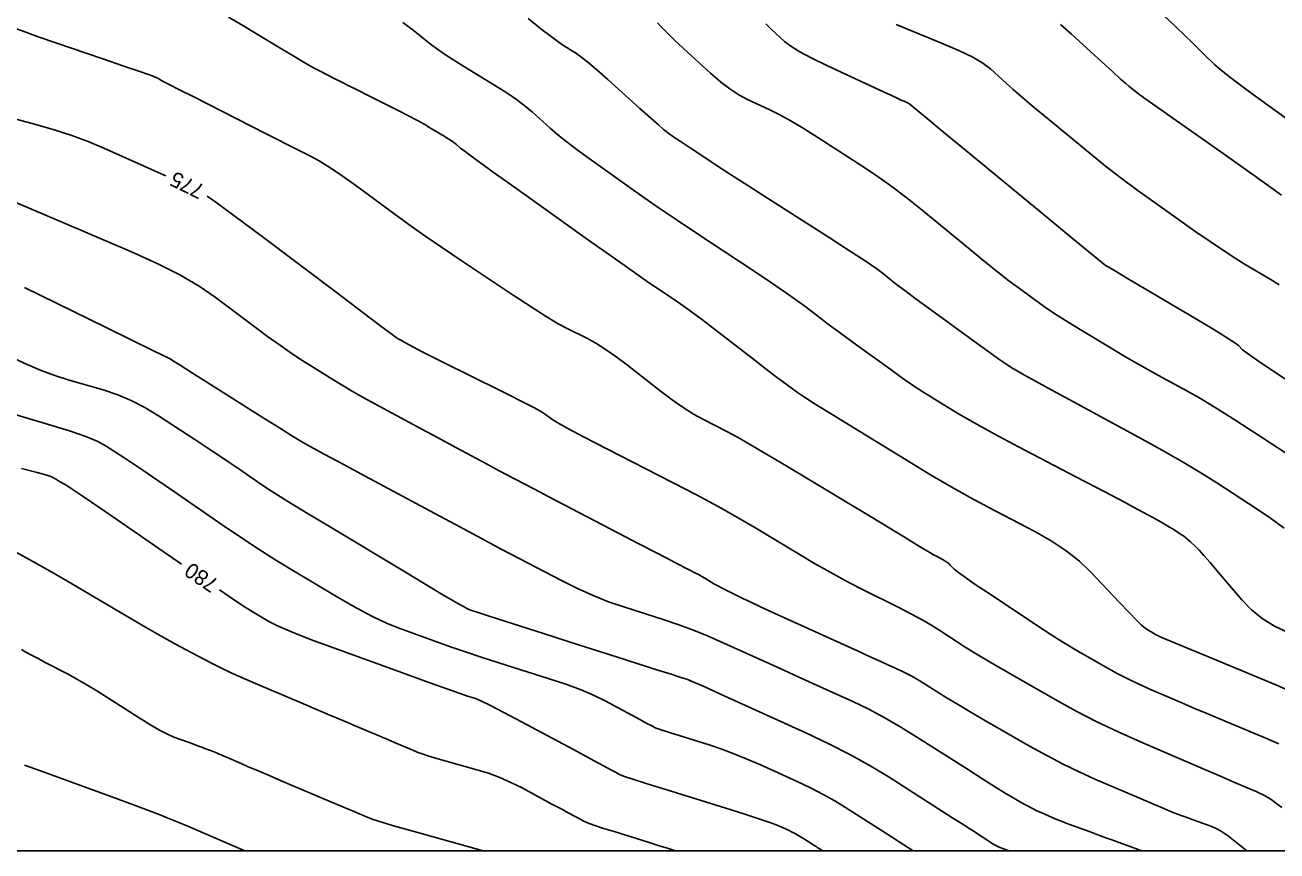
# Model space of a CAD drawing. Extents: x 2082232 to 2083549, y 592624 to 593832.
# Drawn here: x 2082311.6 to 2082368.9, y 592623.8 to 592661.6 of the extents above; entities that cross this region are included whole.
import ezdxf

# ---------------------------------------------------------------- set-up
doc = ezdxf.new("R2010")
doc.units = 0
for name, color, linetype in [('DT_X_Contour_Major', 7, 'Continuous'), ('DT_X_Contour_Minor', 7, 'Continuous'), ('DT_X_TIN_Hull', 7, 'Continuous')]:
    doc.layers.add(name, color=color, linetype=linetype)

msp = doc.modelspace()

# ---------------------------------------------------------------- linework, layer by layer
at = {"layer": 'DT_X_Contour_Major'}
for points in [[(2082340.527, 592661.707), (2082340.704, 592661.507), (2082340.963, 592661.244), (2082341.303, 592660.917), (2082341.725, 592660.527), (2082342.957, 592659.402), (2082343.409, 592659.01), (2082343.842, 592658.68), (2082344.255, 592658.41), (2082344.649, 592658.201), (2082345.672, 592657.726), (2082346.096, 592657.513), (2082346.603, 592657.231), (2082347.192, 592656.88), (2082347.862, 592656.459), (2082349.76, 592655.243), (2082350.479, 592654.766), (2082351.211, 592654.244), (2082351.958, 592653.678), (2082352.719, 592653.069), (2082354.766, 592651.384), (2082355.484, 592650.798), (2082356.101, 592650.303), (2082356.618, 592649.9), (2082357.035, 592649.588), (2082358.013, 592648.878), (2082358.404, 592648.603), (2082358.845, 592648.31), (2082359.335, 592647.998), (2082359.874, 592647.669), (2082361.377, 592646.765), (2082361.93, 592646.436), (2082362.462, 592646.128), (2082362.972, 592645.838), (2082363.461, 592645.569), (2082364.735, 592644.878), (2082365.307, 592644.552), (2082366.065, 592644.091), (2082367.009, 592643.495), (2082368.14, 592642.766), (2082371.406, 592640.64)], [(2082309.776, 592657.658), (2082312.069, 592657.052), (2082312.908, 592656.814), (2082313.706, 592656.555), (2082314.462, 592656.275), (2082315.177, 592655.973), (2082317.028, 592655.142), (2082317.66, 592654.858), (2082318.023, 592654.696)], [(2082319.902, 592653.772), (2082320.298, 592653.499), (2082321.194, 592652.847), (2082322.37, 592651.969), (2082325.875, 592649.324), (2082327.03, 592648.454), (2082327.863, 592647.826), (2082328.376, 592647.442), (2082328.568, 592647.301), (2082328.652, 592647.247), (2082328.707, 592647.215), (2082328.81, 592647.158), (2082328.96, 592647.077), (2082329.157, 592646.97), (2082329.746, 592646.653), (2082330.033, 592646.503), (2082330.452, 592646.29), (2082331.003, 592646.015), (2082331.686, 592645.677), (2082333.684, 592644.691), (2082334.353, 592644.357), (2082334.862, 592644.095), (2082335.211, 592643.903), (2082335.4, 592643.783), (2082335.689, 592643.558), (2082335.927, 592643.411), (2082336.421, 592643.139), (2082337.173, 592642.742), (2082338.183, 592642.221), (2082341.217, 592640.665), (2082342.307, 592640.098), (2082343.298, 592639.564), (2082344.192, 592639.064), (2082344.989, 592638.597), (2082346.982, 592637.396), (2082347.719, 592636.96), (2082348.433, 592636.555), (2082349.124, 592636.179), (2082349.793, 592635.833), (2082351.548, 592634.95), (2082352.16, 592634.636), (2082352.683, 592634.355), (2082353.114, 592634.107), (2082353.456, 592633.893), (2082354.245, 592633.367), (2082354.612, 592633.133), (2082355.118, 592632.825), (2082355.765, 592632.444), (2082356.553, 592631.988), (2082358.84, 592630.675), (2082359.72, 592630.189), (2082360.646, 592629.713), (2082361.618, 592629.248), (2082362.636, 592628.793), (2082365.41, 592627.596), (2082366.333, 592627.199), (2082367.018, 592626.904), (2082367.467, 592626.711), (2082367.68, 592626.62), (2082367.932, 592626.516), (2082368.025, 592626.476), (2082368.115, 592626.434), (2082368.202, 592626.391), (2082368.285, 592626.347), (2082368.505, 592626.227), (2082368.627, 592626.147), (2082368.828, 592625.999), (2082369.107, 592625.781)], [(2082311.403, 592641.311), (2082312.118, 592641.123), (2082312.565, 592641), (2082312.744, 592640.944), (2082312.866, 592640.881), (2082312.92, 592640.852), (2082312.99, 592640.812), (2082313.078, 592640.762), (2082313.182, 592640.701), (2082313.483, 592640.524), (2082313.726, 592640.366), (2082314.229, 592640.027), (2082314.992, 592639.506), (2082316.016, 592638.803), (2082318.738, 592636.93)], [(2082320.472, 592635.744), (2082320.966, 592635.41), (2082321.576, 592635.005), (2082321.968, 592634.757), (2082322.726, 592634.303), (2082323.127, 592634.098), (2082323.764, 592633.826), (2082324.637, 592633.485), (2082325.745, 592633.075), (2082329.014, 592631.893), (2082330.106, 592631.498), (2082330.93, 592631.202), (2082331.488, 592631.005), (2082331.778, 592630.906), (2082332.194, 592630.774), (2082332.443, 592630.67), (2082332.875, 592630.459), (2082333.492, 592630.141), (2082334.293, 592629.715), (2082336.674, 592628.435), (2082337.464, 592628.01), (2082338.049, 592627.696), (2082338.428, 592627.492), (2082338.601, 592627.399), (2082338.79, 592627.298), (2082338.978, 592627.225), (2082339.402, 592627.083), (2082340.061, 592626.872), (2082340.956, 592626.592), (2082343.656, 592625.752), (2082344.564, 592625.466), (2082345.264, 592625.239), (2082345.756, 592625.07), (2082346.039, 592624.959), (2082346.518, 592624.742), (2082346.692, 592624.66), (2082346.853, 592624.577), (2082347.003, 592624.494), (2082347.142, 592624.41), (2082347.495, 592624.184), (2082347.612, 592624.109), (2082347.7, 592624.053), (2082347.759, 592624.015), (2082347.788, 592623.996), (2082347.844, 592623.96), (2082347.894, 592623.927), (2082348.091, 592623.798)]]:
    msp.add_lwpolyline(points, dxfattribs=at)
at = {"layer": 'DT_X_Contour_Minor'}
for points in [[(2082363.073, 592662.646), (2082364.254, 592661.516), (2082364.666, 592661.122), (2082365.016, 592660.786), (2082365.304, 592660.509), (2082365.529, 592660.291), (2082366.048, 592659.786), (2082366.328, 592659.541), (2082366.781, 592659.184), (2082367.405, 592658.715), (2082368.201, 592658.134), (2082370.553, 592656.435)], [(2082320.884, 592661.97), (2082321.542, 592661.589), (2082323.277, 592660.535), (2082323.878, 592660.173), (2082324.379, 592659.878), (2082324.78, 592659.65), (2082325.082, 592659.489), (2082325.754, 592659.147), (2082326.039, 592659.003), (2082326.389, 592658.826), (2082326.804, 592658.617), (2082327.284, 592658.376), (2082328.652, 592657.689), (2082329.129, 592657.446), (2082329.537, 592657.231), (2082329.874, 592657.046), (2082330.14, 592656.89), (2082330.757, 592656.512), (2082330.967, 592656.38), (2082331.135, 592656.271), (2082331.261, 592656.183), (2082331.344, 592656.116), (2082331.509, 592655.967), (2082331.717, 592655.809), (2082332.216, 592655.445), (2082333.007, 592654.876), (2082334.09, 592654.102), (2082337.365, 592651.764), (2082338.478, 592650.972), (2082339.36, 592650.348), (2082340.011, 592649.894), (2082340.431, 592649.608), (2082341.243, 592649.071), (2082341.59, 592648.832), (2082342.022, 592648.52), (2082342.538, 592648.135), (2082343.139, 592647.676), (2082344.854, 592646.353), (2082345.438, 592645.904), (2082345.904, 592645.548), (2082346.252, 592645.285), (2082346.481, 592645.115), (2082346.935, 592644.786), (2082347.212, 592644.6), (2082347.701, 592644.288), (2082348.403, 592643.851), (2082349.317, 592643.288), (2082352.038, 592641.619), (2082353.031, 592641.02), (2082353.967, 592640.472), (2082354.848, 592639.977), (2082355.673, 592639.535), (2082357.797, 592638.424), (2082358.556, 592637.995), (2082359.238, 592637.54), (2082359.843, 592637.06), (2082360.372, 592636.554), (2082361.681, 592635.171), (2082362.119, 592634.711), (2082362.451, 592634.37), (2082362.678, 592634.147), (2082362.799, 592634.042), (2082362.982, 592633.92), (2082363.047, 592633.877), (2082363.106, 592633.839), (2082363.159, 592633.807), (2082363.206, 592633.779), (2082363.321, 592633.713), (2082363.366, 592633.688), (2082363.413, 592633.664), (2082363.462, 592633.64), (2082363.514, 592633.617), (2082363.654, 592633.557), (2082363.836, 592633.48), (2082364.278, 592633.296), (2082364.978, 592633.004), (2082365.937, 592632.605), (2082368.841, 592631.398), (2082369.912, 592630.936)], [(2082328.861, 592661.72), (2082329.154, 592661.503), (2082329.415, 592661.306), (2082329.641, 592661.129), (2082330.2, 592660.684), (2082330.45, 592660.498), (2082330.782, 592660.27), (2082331.195, 592660.003), (2082331.689, 592659.695), (2082333.116, 592658.82), (2082333.623, 592658.499), (2082334.072, 592658.191), (2082334.463, 592657.896), (2082334.798, 592657.614), (2082335.613, 592656.879), (2082335.96, 592656.581), (2082336.392, 592656.238), (2082336.907, 592655.848), (2082337.506, 592655.414), (2082339.216, 592654.193), (2082339.894, 592653.716), (2082340.645, 592653.198), (2082341.469, 592652.64), (2082342.366, 592652.043), (2082344.856, 592650.395), (2082345.708, 592649.829), (2082346.393, 592649.364), (2082346.913, 592649.002), (2082347.268, 592648.741), (2082347.992, 592648.183), (2082348.3, 592647.949), (2082348.68, 592647.665), (2082349.133, 592647.332), (2082349.659, 592646.95), (2082351.157, 592645.865), (2082351.702, 592645.477), (2082352.21, 592645.126), (2082352.683, 592644.812), (2082353.12, 592644.536), (2082354.239, 592643.85), (2082354.729, 592643.561), (2082355.361, 592643.207), (2082356.136, 592642.788), (2082357.052, 592642.304), (2082359.683, 592640.929), (2082360.589, 592640.455), (2082361.33, 592640.065), (2082361.908, 592639.759), (2082362.322, 592639.537), (2082363.208, 592639.057), (2082363.514, 592638.889), (2082363.771, 592638.744), (2082363.976, 592638.624), (2082364.131, 592638.527), (2082364.478, 592638.302), (2082364.603, 592638.217), (2082364.721, 592638.13), (2082364.831, 592638.041), (2082364.933, 592637.95), (2082365.195, 592637.706), (2082365.331, 592637.566), (2082365.544, 592637.329), (2082365.835, 592636.996), (2082366.202, 592636.567), (2082367.283, 592635.294), (2082367.72, 592634.842), (2082368.219, 592634.441), (2082368.781, 592634.091), (2082369.406, 592633.793)], [(2082334.599, 592661.901), (2082335.186, 592661.439), (2082335.659, 592661.075), (2082336.019, 592660.81), (2082336.266, 592660.644), (2082336.773, 592660.334), (2082337.008, 592660.17), (2082337.333, 592659.912), (2082337.747, 592659.559), (2082338.252, 592659.111), (2082339.717, 592657.791), (2082340.204, 592657.354), (2082340.568, 592657.03), (2082340.807, 592656.82), (2082340.923, 592656.725), (2082341.066, 592656.622), (2082341.158, 592656.56), (2082341.324, 592656.448), (2082341.565, 592656.287), (2082341.882, 592656.078), (2082342.825, 592655.454), (2082343.265, 592655.166), (2082343.876, 592654.769), (2082344.66, 592654.265), (2082345.615, 592653.652), (2082348.392, 592651.874), (2082349.324, 592651.274), (2082350.036, 592650.807), (2082350.528, 592650.473), (2082350.801, 592650.273), (2082351.235, 592649.915), (2082351.47, 592649.731), (2082351.847, 592649.447), (2082352.368, 592649.064), (2082353.032, 592648.58), (2082354.993, 592647.157), (2082355.653, 592646.68), (2082356.162, 592646.317), (2082356.519, 592646.068), (2082356.726, 592645.932), (2082357.074, 592645.723), (2082357.328, 592645.578), (2082357.829, 592645.302), (2082358.576, 592644.894), (2082359.57, 592644.354), (2082362.548, 592642.739), (2082363.61, 592642.154), (2082364.562, 592641.61), (2082365.404, 592641.108), (2082366.136, 592640.647), (2082367.942, 592639.471), (2082368.598, 592639.026), (2082369.213, 592638.571)], [(2082311.149, 592661.448), (2082312.221, 592661.046), (2082315.131, 592660.056), (2082316.09, 592659.729), (2082316.787, 592659.492), (2082317.221, 592659.343), (2082317.391, 592659.282), (2082317.496, 592659.241), (2082317.534, 592659.224), (2082317.572, 592659.206), (2082317.609, 592659.187), (2082317.645, 592659.166), (2082317.74, 592659.108), (2082317.864, 592659.042), (2082318.164, 592658.888), (2082318.639, 592658.645), (2082319.291, 592658.313), (2082321.264, 592657.311), (2082321.961, 592656.957), (2082322.573, 592656.647), (2082323.1, 592656.381), (2082323.541, 592656.159), (2082324.605, 592655.624), (2082325.036, 592655.388), (2082325.53, 592655.082), (2082326.088, 592654.706), (2082326.71, 592654.259), (2082328.452, 592652.974), (2082329.135, 592652.478), (2082329.877, 592651.954), (2082330.679, 592651.403), (2082331.54, 592650.823), (2082333.917, 592649.24), (2082334.74, 592648.7), (2082335.428, 592648.264), (2082335.98, 592647.934), (2082336.397, 592647.709), (2082337.329, 592647.25), (2082337.704, 592647.044), (2082338.134, 592646.772), (2082338.617, 592646.434), (2082339.153, 592646.028), (2082340.654, 592644.859), (2082341.198, 592644.449), (2082341.704, 592644.096), (2082342.172, 592643.8), (2082342.602, 592643.56), (2082343.698, 592642.998), (2082344.183, 592642.738), (2082344.817, 592642.379), (2082345.601, 592641.921), (2082346.532, 592641.364), (2082349.216, 592639.747), (2082350.131, 592639.196), (2082350.864, 592638.753), (2082351.415, 592638.419), (2082351.784, 592638.194), (2082352.525, 592637.74), (2082352.781, 592637.584), (2082352.995, 592637.456), (2082353.167, 592637.357), (2082353.296, 592637.286), (2082353.583, 592637.136), (2082353.686, 592637.078), (2082353.778, 592637.017), (2082353.86, 592636.952), (2082353.932, 592636.883), (2082354.109, 592636.696), (2082354.256, 592636.576), (2082354.564, 592636.354), (2082355.032, 592636.032), (2082355.662, 592635.609), (2082357.557, 592634.347), (2082358.235, 592633.901), (2082358.848, 592633.508), (2082359.396, 592633.169), (2082359.879, 592632.884), (2082361.081, 592632.194), (2082361.543, 592631.938), (2082362.03, 592631.688), (2082362.54, 592631.444), (2082363.075, 592631.205), (2082364.532, 592630.577), (2082365.084, 592630.339), (2082365.648, 592630.1), (2082366.223, 592629.858), (2082366.809, 592629.613), (2082368.386, 592628.957), (2082368.969, 592628.706)], [(2082345.482, 592661.658), (2082345.736, 592661.409), (2082346.34, 592660.857), (2082346.631, 592660.633), (2082347.05, 592660.375), (2082347.598, 592660.082), (2082348.275, 592659.755), (2082350.25, 592658.838), (2082350.904, 592658.534), (2082351.383, 592658.313), (2082351.689, 592658.172), (2082351.82, 592658.113), (2082351.939, 592658.065), (2082351.98, 592658.048), (2082352.013, 592658.031), (2082352.038, 592658.017), (2082352.056, 592658.003), (2082352.094, 592657.969), (2082352.273, 592657.82), (2082352.782, 592657.4), (2082353.622, 592656.708), (2082354.791, 592655.744), (2082358.351, 592652.812), (2082359.519, 592651.849), (2082360.355, 592651.161), (2082360.858, 592650.747), (2082361.028, 592650.607), (2082361.039, 592650.599), (2082361.154, 592650.531), (2082361.49, 592650.332), (2082362.049, 592650.001), (2082362.829, 592649.54), (2082365.204, 592648.135), (2082365.993, 592647.665), (2082366.576, 592647.308), (2082366.955, 592647.064), (2082367.128, 592646.934), (2082367.318, 592646.738), (2082367.524, 592646.579), (2082368, 592646.248), (2082368.746, 592645.745), (2082369.762, 592645.071)], [(2082351.46, 592661.624), (2082353.612, 592660.747), (2082354.352, 592660.429), (2082354.958, 592660.13), (2082355.43, 592659.853), (2082355.768, 592659.595), (2082356.49, 592658.937), (2082356.816, 592658.648), (2082357.25, 592658.275), (2082357.794, 592657.818), (2082358.446, 592657.278), (2082360.332, 592655.724), (2082361.042, 592655.15), (2082361.756, 592654.595), (2082362.475, 592654.057), (2082363.199, 592653.537), (2082365.136, 592652.174), (2082365.825, 592651.695), (2082366.438, 592651.282), (2082366.976, 592650.933), (2082367.439, 592650.649), (2082368.574, 592649.978), (2082368.99, 592649.712)], [(2082358.981, 592661.623), (2082359.479, 592661.188), (2082360.886, 592659.905), (2082361.358, 592659.476), (2082361.718, 592659.15), (2082361.966, 592658.929), (2082362.101, 592658.811), (2082362.314, 592658.636), (2082362.487, 592658.506), (2082362.846, 592658.247), (2082363.392, 592657.86), (2082364.125, 592657.343), (2082366.327, 592655.794), (2082367.119, 592655.235), (2082367.845, 592654.72), (2082368.504, 592654.25), (2082369.096, 592653.824)], [(2082311.148, 592653.488), (2082311.97, 592653.136), (2082313.083, 592652.66), (2082316.44, 592651.226), (2082317.624, 592650.693), (2082318.658, 592650.169), (2082319.543, 592649.656), (2082320.279, 592649.153), (2082322.041, 592647.823), (2082322.677, 592647.35), (2082323.265, 592646.929), (2082323.804, 592646.558), (2082324.294, 592646.239), (2082325.537, 592645.455), (2082326.016, 592645.159), (2082326.522, 592644.86), (2082327.054, 592644.558), (2082327.614, 592644.251), (2082329.14, 592643.43), (2082329.706, 592643.126), (2082330.258, 592642.829), (2082330.796, 592642.54), (2082331.32, 592642.257), (2082332.7, 592641.515), (2082333.285, 592641.202), (2082334.008, 592640.82), (2082334.868, 592640.368), (2082335.865, 592639.847), (2082338.707, 592638.365), (2082339.67, 592637.864), (2082340.427, 592637.469), (2082340.98, 592637.183), (2082341.327, 592637.004), (2082341.978, 592636.67), (2082342.206, 592636.552), (2082342.4, 592636.448), (2082342.561, 592636.359), (2082342.689, 592636.285), (2082342.984, 592636.107), (2082343.114, 592636.032), (2082343.282, 592635.941), (2082343.487, 592635.834), (2082343.73, 592635.71), (2082344.428, 592635.359), (2082344.763, 592635.195), (2082345.245, 592634.969), (2082345.873, 592634.679), (2082346.647, 592634.327), (2082348.907, 592633.303), (2082349.678, 592632.954), (2082350.294, 592632.674), (2082350.757, 592632.464), (2082351.066, 592632.324), (2082351.686, 592632.043), (2082351.924, 592631.928), (2082352.174, 592631.795), (2082352.435, 592631.644), (2082352.709, 592631.475), (2082353.455, 592630.998), (2082353.795, 592630.787), (2082354.258, 592630.51), (2082354.842, 592630.168), (2082355.548, 592629.76), (2082357.594, 592628.586), (2082358.354, 592628.162), (2082359.101, 592627.771), (2082359.834, 592627.414), (2082360.554, 592627.09), (2082362.456, 592626.27), (2082363.097, 592625.994), (2082363.596, 592625.782), (2082363.952, 592625.634), (2082364.165, 592625.55), (2082364.542, 592625.412), (2082364.693, 592625.356), (2082365.055, 592625.223), (2082365.855, 592624.93), (2082366.071, 592624.84), (2082366.278, 592624.735), (2082366.475, 592624.614), (2082366.663, 592624.476), (2082367.517, 592623.798)], [(2082311.538, 592649.594), (2082315.261, 592647.768), (2082316.485, 592647.168), (2082317.365, 592646.737), (2082317.9, 592646.476), (2082318.09, 592646.383), (2082318.138, 592646.363), (2082318.154, 592646.355), (2082318.168, 592646.349), (2082318.179, 592646.342), (2082318.188, 592646.337), (2082318.207, 592646.323), (2082318.325, 592646.247), (2082318.667, 592646.031), (2082319.232, 592645.674), (2082320.021, 592645.177), (2082322.421, 592643.662), (2082323.219, 592643.16), (2082323.811, 592642.79), (2082324.197, 592642.55), (2082324.378, 592642.443), (2082324.587, 592642.33), (2082325.303, 592641.945), (2082326.081, 592641.527), (2082327.138, 592640.958), (2082330.331, 592639.24), (2082331.47, 592638.629), (2082332.492, 592638.083), (2082333.398, 592637.603), (2082334.187, 592637.189), (2082336.137, 592636.172), (2082336.863, 592635.811), (2082337.579, 592635.49), (2082338.286, 592635.208), (2082338.982, 592634.966), (2082340.826, 592634.374), (2082341.507, 592634.146), (2082342.168, 592633.903), (2082342.809, 592633.647), (2082343.429, 592633.377), (2082345.057, 592632.64), (2082345.676, 592632.359), (2082346.314, 592632.07), (2082346.969, 592631.772), (2082347.644, 592631.466), (2082349.465, 592630.639), (2082350.166, 592630.302), (2082350.901, 592629.911), (2082351.672, 592629.466), (2082352.477, 592628.967), (2082354.67, 592627.566), (2082355.416, 592627.091), (2082356.008, 592626.718), (2082356.447, 592626.446), (2082356.731, 592626.276), (2082357.286, 592625.958), (2082357.492, 592625.843), (2082357.694, 592625.737), (2082357.893, 592625.64), (2082358.088, 592625.552), (2082358.603, 592625.33), (2082358.812, 592625.243), (2082359.051, 592625.147), (2082359.321, 592625.043), (2082359.621, 592624.931), (2082360.463, 592624.622), (2082360.77, 592624.509), (2082361.058, 592624.403), (2082361.328, 592624.304), (2082362.707, 592623.798)], [(2082311.036, 592646.356), (2082311.672, 592646.06), (2082312.303, 592645.796), (2082312.928, 592645.566), (2082313.549, 592645.369), (2082315.196, 592644.889), (2082315.815, 592644.68), (2082316.435, 592644.415), (2082317.057, 592644.093), (2082317.68, 592643.714), (2082319.344, 592642.629), (2082319.938, 592642.241), (2082320.471, 592641.888), (2082320.944, 592641.571), (2082321.356, 592641.291), (2082322.373, 592640.591), (2082322.859, 592640.269), (2082323.556, 592639.83), (2082324.463, 592639.274), (2082325.58, 592638.599), (2082328.838, 592636.645), (2082329.915, 592635.999), (2082330.703, 592635.527), (2082331.202, 592635.231), (2082331.412, 592635.108), (2082331.585, 592635.015), (2082331.646, 592634.982), (2082331.699, 592634.954), (2082331.742, 592634.931), (2082331.778, 592634.912), (2082331.86, 592634.869), (2082331.988, 592634.823), (2082332.31, 592634.716), (2082332.826, 592634.548), (2082333.536, 592634.319), (2082335.687, 592633.629), (2082336.48, 592633.374), (2082337.245, 592633.13), (2082337.983, 592632.895), (2082338.692, 592632.669), (2082340.547, 592632.08), (2082341.157, 592631.885), (2082341.598, 592631.744), (2082341.869, 592631.655), (2082341.971, 592631.62), (2082342.054, 592631.575), (2082342.058, 592631.574), (2082342.066, 592631.571), (2082342.078, 592631.567), (2082342.144, 592631.546), (2082342.298, 592631.479), (2082342.723, 592631.288), (2082343.417, 592630.974), (2082344.381, 592630.536), (2082347.314, 592629.204), (2082348.378, 592628.702), (2082349.369, 592628.196), (2082350.288, 592627.685), (2082351.136, 592627.169), (2082354.009, 592625.333), (2082354.517, 592625.008), (2082354.824, 592624.812), (2082354.928, 592624.746), (2082355.126, 592624.616), (2082355.7, 592624.24), (2082355.853, 592624.143), (2082355.988, 592624.064), (2082356.105, 592624.002), (2082356.205, 592623.959), (2082356.627, 592623.798)], [(2082310.279, 592644.014), (2082312.793, 592643.281), (2082313.656, 592643.015), (2082314.36, 592642.769), (2082314.903, 592642.542), (2082315.286, 592642.335), (2082316.096, 592641.807), (2082316.466, 592641.562), (2082316.969, 592641.223), (2082317.604, 592640.79), (2082318.373, 592640.262), (2082320.599, 592638.731), (2082321.429, 592638.168), (2082322.249, 592637.63), (2082323.06, 592637.116), (2082323.861, 592636.626), (2082325.984, 592635.352), (2082326.756, 592634.907), (2082327.478, 592634.527), (2082328.151, 592634.213), (2082328.775, 592633.963), (2082330.372, 592633.385), (2082331.002, 592633.162), (2082331.695, 592632.925), (2082332.449, 592632.676), (2082333.266, 592632.413), (2082335.527, 592631.695), (2082336.325, 592631.429), (2082337.026, 592631.169), (2082337.628, 592630.915), (2082338.132, 592630.667), (2082339.747, 592629.799), (2082340.045, 592629.639), (2082340.238, 592629.535), (2082340.326, 592629.488), (2082340.422, 592629.436), (2082340.518, 592629.399), (2082340.734, 592629.327), (2082341.07, 592629.22), (2082341.525, 592629.077), (2082342.9, 592628.649), (2082343.431, 592628.473), (2082343.993, 592628.263), (2082344.586, 592628.022), (2082345.21, 592627.748), (2082346.916, 592626.973), (2082347.535, 592626.681), (2082348.111, 592626.387), (2082348.646, 592626.089), (2082349.139, 592625.789), (2082350.811, 592624.721), (2082351.291, 592624.414), (2082351.358, 592624.371), (2082351.382, 592624.355), (2082352.233, 592623.798)], [(2082310.873, 592637.626), (2082311.795, 592637.123), (2082312.727, 592636.598), (2082313.67, 592636.05), (2082316.199, 592634.559), (2082317.082, 592634.042), (2082317.834, 592633.61), (2082318.455, 592633.261), (2082318.945, 592632.997), (2082320.078, 592632.406), (2082320.538, 592632.174), (2082321.067, 592631.924), (2082321.665, 592631.655), (2082322.333, 592631.368), (2082324.206, 592630.576), (2082324.888, 592630.288), (2082325.528, 592630.017), (2082326.126, 592629.764), (2082326.682, 592629.528), (2082328.109, 592628.923), (2082328.588, 592628.72), (2082328.957, 592628.563), (2082329.214, 592628.454), (2082329.361, 592628.392), (2082329.603, 592628.289), (2082329.749, 592628.237), (2082330.005, 592628.157), (2082330.37, 592628.05), (2082330.846, 592627.915), (2082332.26, 592627.518), (2082332.787, 592627.354), (2082333.307, 592627.16), (2082333.819, 592626.936), (2082334.325, 592626.682), (2082335.663, 592625.962), (2082336.115, 592625.719), (2082336.468, 592625.53), (2082336.722, 592625.393), (2082336.877, 592625.31), (2082337.158, 592625.159), (2082337.323, 592625.086), (2082337.608, 592624.983), (2082338.013, 592624.848), (2082338.537, 592624.682), (2082340.096, 592624.197), (2082340.609, 592624.037), (2082340.981, 592623.922), (2082341.211, 592623.85), (2082341.299, 592623.823), (2082341.38, 592623.798)], [(2082311.41, 592633.02), (2082311.612, 592632.904), (2082311.864, 592632.765), (2082312.168, 592632.602), (2082312.522, 592632.415), (2082313.537, 592631.885), (2082313.936, 592631.669), (2082314.374, 592631.416), (2082314.851, 592631.128), (2082315.365, 592630.803), (2082316.789, 592629.89), (2082317.289, 592629.579), (2082317.721, 592629.329), (2082318.085, 592629.14), (2082318.382, 592629.013), (2082319.083, 592628.757), (2082319.322, 592628.669), (2082319.515, 592628.599), (2082319.661, 592628.545), (2082319.76, 592628.509), (2082319.963, 592628.434), (2082320.066, 592628.395), (2082320.222, 592628.33), (2082320.43, 592628.242), (2082320.692, 592628.13), (2082321.462, 592627.798), (2082321.793, 592627.655), (2082322.211, 592627.477), (2082322.714, 592627.262), (2082323.304, 592627.012), (2082324.991, 592626.297), (2082325.57, 592626.051), (2082326.044, 592625.85), (2082326.411, 592625.695), (2082326.672, 592625.584), (2082327.228, 592625.348), (2082327.502, 592625.245), (2082327.908, 592625.113), (2082328.446, 592624.951), (2082329.115, 592624.759), (2082332.545, 592623.798)], [(2082311.545, 592627.731), (2082312.271, 592627.466), (2082315.213, 592626.39), (2082315.83, 592626.164), (2082316.655, 592625.862), (2082317.393, 592625.592), (2082317.704, 592625.473), (2082318.084, 592625.32), (2082318.534, 592625.133), (2082319.052, 592624.912), (2082321.633, 592623.798)]]:
    msp.add_lwpolyline(points, dxfattribs=at)
at = {"layer": 'DT_X_TIN_Hull'}
msp.add_lwpolyline([(2082307.026, 592623.798), (2082312.923, 592623.798), (2082316.791, 592623.798), (2082324.137, 592623.798), (2082326.678, 592623.798), (2082335.245, 592623.798), (2082336.473, 592623.798), (2082345.605, 592623.798), (2082346.277, 592623.798), (2082346.46, 592623.798), (2082355.746, 592623.798), (2082358.691, 592623.798), (2082365.127, 592623.798), (2082370.879, 592623.798)], dxfattribs=at)

# ---------------------------------------------------------------- texts
at = {"layer": 'DT_X_Contour_Major'}
for s, rotation, p in [('775', 153.79494, (2082319.844, 592654.242)), ('780', 145.62451, (2082320.48, 592636.161))]:
    msp.add_text(s, height=0.7, rotation=rotation, dxfattribs=at).set_placement(p)

doc.saveas('drawing.dxf')
